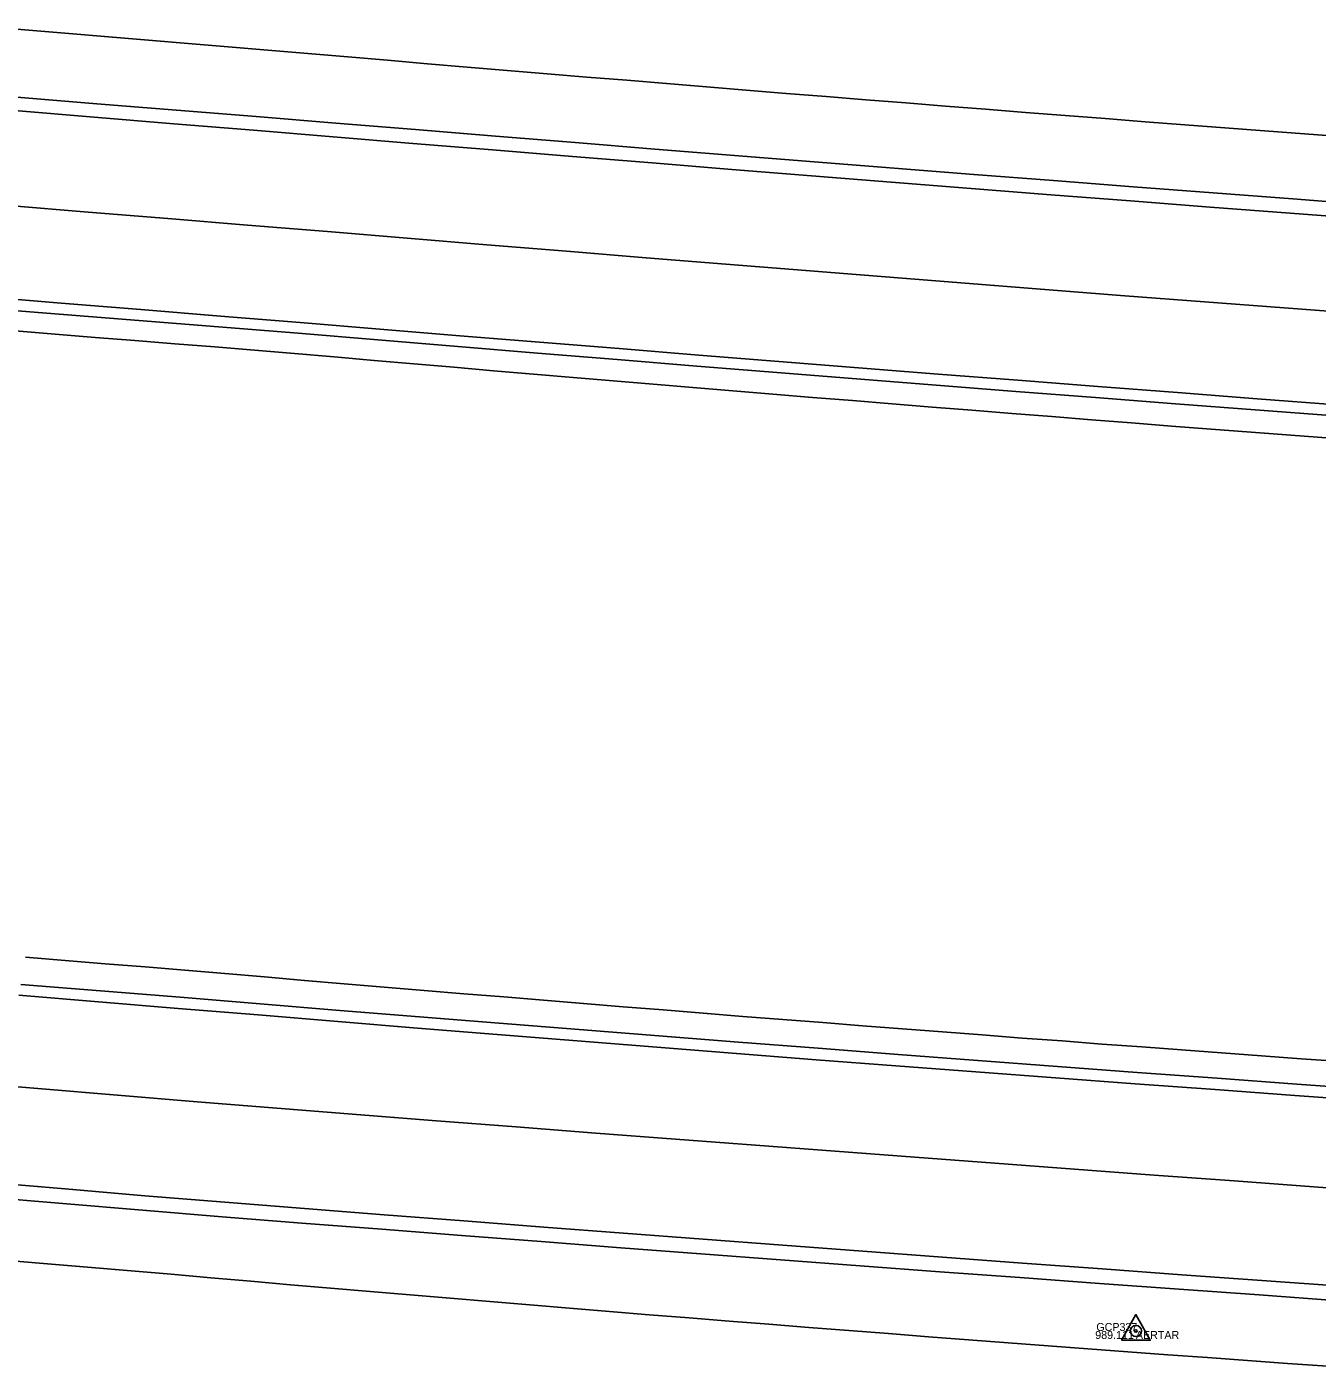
# Model space of a CAD drawing. Extents: x 2065431 to 2068157, y 709104 to 709719.
# Drawn here: x 2067834.4 to 2067995.7, y 709227.6 to 709395.1 of the extents above; entities that cross this region are included whole.
import ezdxf

# ---------------------------------------------------------------- set-up
doc = ezdxf.new("R2010")
doc.units = 0
for name, color, linetype in [('DT_X_Terrain_Boundary', 7, 'Continuous'), ('PM_X_Edge_Line', 7, 'Continuous'), ('PM_X_Lane_Line', 7, 'Continuous'), ('PV_X_EOP', 7, 'Continuous'), ('PV_X_Shoulder_Rumble_Strip', 7, 'Continuous'), ('SV_P_Aerial_Targets', 7, 'Continuous'), ('SV_X_Mon_Cells_Found', 7, 'Continuous'), ('SV_X_Text_Elevation', 7, 'Continuous'), ('SV_X_Text_Name', 7, 'Continuous')]:
    doc.layers.add(name, color=color, linetype=linetype)

msp = doc.modelspace()

# ---------------------------------------------------------------- linework, layer by layer
at = {"layer": 'DT_X_Terrain_Boundary'}
for points in [[(2067999.13, 709381.3), (2067994.14, 709381.67), (2067989.15, 709382.05), (2067984.17, 709382.43), (2067979.18, 709382.81), (2067974.2, 709383.19), (2067969.21, 709383.58), (2067964.23, 709383.97), (2067959.24, 709384.36), (2067954.26, 709384.75), (2067949.27, 709385.14), (2067944.29, 709385.54), (2067939.3, 709385.93), (2067934.32, 709386.33), (2067929.34, 709386.74), (2067924.35, 709387.14), (2067919.37, 709387.55), (2067914.39, 709387.96), (2067909.4, 709388.37), (2067904.42, 709388.78), (2067899.44, 709389.2), (2067894.46, 709389.61), (2067889.47, 709390.03), (2067884.49, 709390.45), (2067879.51, 709390.88), (2067874.53, 709391.3), (2067869.55, 709391.73), (2067864.56, 709392.15), (2067859.58, 709392.57), (2067854.6, 709392.98), (2067849.61, 709393.4), (2067844.63, 709393.81), (2067839.65, 709394.23), (2067834.67, 709394.64), (2067829.68, 709395.06)], [(2067832.97, 709357.04), (2067837.96, 709356.64), (2067842.94, 709356.24), (2067847.93, 709355.85), (2067852.91, 709355.45), (2067857.9, 709355.06), (2067862.88, 709354.66), (2067867.86, 709354.23), (2067872.84, 709353.79), (2067877.82, 709353.36), (2067882.8, 709352.93), (2067887.79, 709352.5), (2067892.77, 709352.07), (2067897.75, 709351.65), (2067902.73, 709351.23), (2067907.71, 709350.81), (2067912.7, 709350.39), (2067917.68, 709349.97), (2067922.66, 709349.56), (2067927.65, 709349.15), (2067932.63, 709348.74), (2067937.61, 709348.33), (2067942.6, 709347.93), (2067947.58, 709347.52), (2067952.56, 709347.12), (2067957.55, 709346.72), (2067962.53, 709346.33), (2067967.52, 709345.93), (2067972.5, 709345.54), (2067977.49, 709345.15), (2067982.47, 709344.77), (2067987.46, 709344.38), (2067992.44, 709344), (2067997.43, 709343.62)], [(2067998.72, 709265.71), (2067993.73, 709266.07), (2067988.75, 709266.43), (2067983.76, 709266.8), (2067978.77, 709267.17), (2067973.79, 709267.54), (2067968.8, 709267.91), (2067963.82, 709268.29), (2067958.83, 709268.66), (2067953.84, 709269.04), (2067948.86, 709269.43), (2067943.87, 709269.81), (2067938.89, 709270.2), (2067933.9, 709270.59), (2067928.92, 709270.98), (2067923.93, 709271.37), (2067918.95, 709271.77), (2067913.97, 709272.17), (2067908.98, 709272.57), (2067904, 709272.98), (2067899.02, 709273.38), (2067894.03, 709273.79), (2067889.05, 709274.2), (2067884.07, 709274.62), (2067879.08, 709275.03), (2067874.1, 709275.45), (2067869.12, 709275.87), (2067864.14, 709276.3), (2067859.16, 709276.72), (2067854.17, 709277.14), (2067849.19, 709277.54), (2067844.2, 709277.94), (2067839.22, 709278.34), (2067834.24, 709278.75)], [(2067832.52, 709240.82), (2067837.5, 709240.4), (2067842.48, 709239.97), (2067847.46, 709239.55), (2067852.44, 709239.13), (2067857.42, 709238.69), (2067862.41, 709238.26), (2067867.39, 709237.83), (2067872.37, 709237.4), (2067877.35, 709236.97), (2067882.33, 709236.55), (2067887.32, 709236.13), (2067892.3, 709235.72), (2067897.28, 709235.3), (2067902.26, 709234.89), (2067907.25, 709234.48), (2067912.23, 709234.08), (2067917.21, 709233.68), (2067922.2, 709233.28), (2067927.18, 709232.88), (2067932.17, 709232.49), (2067937.15, 709232.1), (2067942.14, 709231.71), (2067947.12, 709231.32), (2067952.11, 709230.94), (2067957.09, 709230.56), (2067962.08, 709230.19), (2067967.06, 709229.81), (2067972.05, 709229.44), (2067977.04, 709229.08), (2067982.02, 709228.71), (2067987.01, 709228.35), (2067992, 709227.99), (2067996.99, 709227.64)]]:
    msp.add_lwpolyline(points, dxfattribs=at)
at = {"layer": 'PM_X_Edge_Line'}
for points in [[(2067832.85, 709384.58), (2067842.81, 709383.76), (2067852.78, 709382.94), (2067862.75, 709382.13), (2067872.71, 709381.31), (2067882.68, 709380.48), (2067892.64, 709379.66), (2067902.61, 709378.85), (2067912.58, 709378.04), (2067922.55, 709377.23), (2067932.51, 709376.44), (2067942.48, 709375.64), (2067952.45, 709374.86), (2067962.42, 709374.07), (2067972.39, 709373.3), (2067982.36, 709372.53), (2067992.33, 709371.76), (2068002.3, 709371)], [(2067828.73, 709361.35), (2067838.7, 709360.53), (2067848.66, 709359.71), (2067858.63, 709358.9), (2067868.6, 709358.09), (2067878.56, 709357.26), (2067888.53, 709356.45), (2067898.5, 709355.64), (2067908.46, 709354.83), (2067918.43, 709354.03), (2067928.4, 709353.24), (2067938.37, 709352.44), (2067948.34, 709351.66), (2067958.31, 709350.88), (2067968.28, 709350.1), (2067978.25, 709349.33), (2067988.22, 709348.57), (2067998.19, 709347.81)], [(2067833.42, 709274.02), (2067843.39, 709273.2), (2067853.35, 709272.37), (2067863.32, 709271.54), (2067873.28, 709270.71), (2067883.25, 709269.9), (2067893.22, 709269.09), (2067903.19, 709268.29), (2067913.15, 709267.5), (2067923.12, 709266.72), (2067933.09, 709265.94), (2067943.06, 709265.18), (2067953.04, 709264.42), (2067963.01, 709263.67), (2067972.98, 709262.94), (2067982.95, 709262.21), (2067992.93, 709261.49), (2068002.9, 709260.77)], [(2067829.26, 709250.65), (2067839.22, 709249.8), (2067849.18, 709248.95), (2067859.15, 709248.13), (2067869.12, 709247.35), (2067879.09, 709246.57), (2067889.06, 709245.79), (2067899.03, 709245.02), (2067909, 709244.26), (2067918.97, 709243.5), (2067928.94, 709242.75), (2067938.92, 709242), (2067948.89, 709241.26), (2067958.86, 709240.53), (2067968.83, 709239.8), (2067978.81, 709239.07), (2067988.78, 709238.36), (2067998.76, 709237.65)]]:
    msp.add_lwpolyline(points, dxfattribs=at)
at = {"layer": 'PM_X_Lane_Line'}
for points in [[(2067832.11, 709372.73), (2067842.08, 709371.91), (2067852.05, 709371.09), (2067862.01, 709370.28), (2067871.98, 709369.47), (2067881.95, 709368.65), (2067891.91, 709367.82), (2067901.88, 709367), (2067911.85, 709366.19), (2067921.81, 709365.38), (2067931.78, 709364.58), (2067941.75, 709363.79), (2067951.72, 709363), (2067961.69, 709362.22), (2067971.66, 709361.45), (2067981.63, 709360.68), (2067991.6, 709359.92), (2068001.57, 709359.17)], [(2067825.81, 709263.2), (2067835.77, 709262.36), (2067845.74, 709261.53), (2067855.71, 709260.7), (2067865.67, 709259.88), (2067875.64, 709259.1), (2067885.61, 709258.32), (2067895.58, 709257.55), (2067905.55, 709256.78), (2067915.52, 709256.02), (2067925.49, 709255.26), (2067935.46, 709254.5), (2067945.44, 709253.75), (2067955.41, 709253), (2067965.38, 709252.26), (2067975.35, 709251.52), (2067985.33, 709250.79), (2067995.3, 709250.05), (2068005.27, 709249.33)]]:
    msp.add_lwpolyline(points, dxfattribs=at)
at = {"layer": 'PV_X_EOP'}
for points in [[(2067829.68, 709395.06), (2067834.67, 709394.64), (2067839.65, 709394.23), (2067844.63, 709393.81), (2067849.61, 709393.4), (2067854.6, 709392.98), (2067859.58, 709392.57), (2067864.56, 709392.15), (2067869.55, 709391.73), (2067874.53, 709391.3), (2067879.51, 709390.88), (2067884.49, 709390.45), (2067889.47, 709390.03), (2067894.46, 709389.61), (2067899.44, 709389.2), (2067904.42, 709388.78), (2067909.4, 709388.37), (2067914.39, 709387.96), (2067919.37, 709387.55), (2067924.35, 709387.14), (2067929.34, 709386.74), (2067934.32, 709386.33), (2067939.3, 709385.93), (2067944.29, 709385.54), (2067949.27, 709385.14), (2067954.26, 709384.75), (2067959.24, 709384.36), (2067964.23, 709383.97), (2067969.21, 709383.58), (2067974.2, 709383.19), (2067979.18, 709382.81), (2067984.17, 709382.43), (2067989.15, 709382.05), (2067994.14, 709381.67), (2067999.13, 709381.3)], [(2067832.97, 709357.04), (2067837.96, 709356.64), (2067842.94, 709356.24), (2067847.93, 709355.85), (2067852.91, 709355.45), (2067857.9, 709355.06), (2067862.88, 709354.66), (2067867.86, 709354.23), (2067872.84, 709353.79), (2067877.82, 709353.36), (2067882.8, 709352.93), (2067887.79, 709352.5), (2067892.77, 709352.07), (2067897.75, 709351.65), (2067902.73, 709351.23), (2067907.71, 709350.81), (2067912.7, 709350.39), (2067917.68, 709349.97), (2067922.66, 709349.56), (2067927.65, 709349.15), (2067932.63, 709348.74), (2067937.61, 709348.33), (2067942.6, 709347.93), (2067947.58, 709347.52), (2067952.56, 709347.12), (2067957.55, 709346.72), (2067962.53, 709346.33), (2067967.52, 709345.93), (2067972.5, 709345.54), (2067977.49, 709345.15), (2067982.47, 709344.77), (2067987.46, 709344.38), (2067992.44, 709344), (2067997.43, 709343.62)], [(2067834.24, 709278.75), (2067839.22, 709278.34), (2067844.2, 709277.94), (2067849.19, 709277.54), (2067854.17, 709277.14), (2067859.16, 709276.72), (2067864.14, 709276.3), (2067869.12, 709275.87), (2067874.1, 709275.45), (2067879.08, 709275.03), (2067884.07, 709274.62), (2067889.05, 709274.2), (2067894.03, 709273.79), (2067899.02, 709273.38), (2067904, 709272.98), (2067908.98, 709272.57), (2067913.97, 709272.17), (2067918.95, 709271.77), (2067923.93, 709271.37), (2067928.92, 709270.98), (2067933.9, 709270.59), (2067938.89, 709270.2), (2067943.87, 709269.81), (2067948.86, 709269.43), (2067953.84, 709269.04), (2067958.83, 709268.66), (2067963.82, 709268.29), (2067968.8, 709267.91), (2067973.79, 709267.54), (2067978.77, 709267.17), (2067983.76, 709266.8), (2067988.75, 709266.43), (2067993.73, 709266.07), (2067998.72, 709265.71)], [(2067832.52, 709240.82), (2067837.5, 709240.4), (2067842.48, 709239.97), (2067847.46, 709239.55), (2067852.44, 709239.13), (2067857.42, 709238.69), (2067862.41, 709238.26), (2067867.39, 709237.83), (2067872.37, 709237.4), (2067877.35, 709236.97), (2067882.33, 709236.55), (2067887.32, 709236.13), (2067892.3, 709235.72), (2067897.28, 709235.3), (2067902.26, 709234.89), (2067907.25, 709234.48), (2067912.23, 709234.08), (2067917.21, 709233.68), (2067922.2, 709233.28), (2067927.18, 709232.88), (2067932.17, 709232.49), (2067937.15, 709232.1), (2067942.14, 709231.71), (2067947.12, 709231.32), (2067952.11, 709230.94), (2067957.09, 709230.56), (2067962.08, 709230.19), (2067967.06, 709229.81), (2067972.05, 709229.44), (2067977.04, 709229.08), (2067982.02, 709228.71), (2067987.01, 709228.35), (2067992, 709227.99), (2067996.99, 709227.64)]]:
    msp.add_lwpolyline(points, dxfattribs=at)
at = {"layer": 'PV_X_Shoulder_Rumble_Strip'}
for points in [[(2067833.18, 709386.26), (2067843.15, 709385.45), (2067853.12, 709384.65), (2067863.08, 709383.85), (2067873.05, 709383.03), (2067883.02, 709382.21), (2067892.98, 709381.39), (2067902.95, 709380.58), (2067912.92, 709379.78), (2067922.89, 709378.98), (2067932.85, 709378.19), (2067942.82, 709377.4), (2067952.79, 709376.61), (2067962.76, 709375.84), (2067972.73, 709375.07), (2067982.7, 709374.3), (2067992.67, 709373.54), (2068002.65, 709372.78)], [(2067828.48, 709359.95), (2067838.44, 709359.14), (2067848.41, 709358.35), (2067858.38, 709357.56), (2067868.35, 709356.75), (2067878.31, 709355.92), (2067888.28, 709355.1), (2067898.25, 709354.28), (2067908.21, 709353.46), (2067918.18, 709352.66), (2067928.15, 709351.86), (2067938.12, 709351.06), (2067948.08, 709350.27), (2067958.05, 709349.49), (2067968.02, 709348.71), (2067977.99, 709347.94), (2067987.96, 709347.18), (2067997.94, 709346.42)], [(2067833.66, 709275.34), (2067843.63, 709274.55), (2067853.6, 709273.75), (2067863.57, 709272.94), (2067873.53, 709272.12), (2067883.5, 709271.31), (2067893.47, 709270.51), (2067903.44, 709269.71), (2067913.4, 709268.93), (2067923.37, 709268.15), (2067933.34, 709267.38), (2067943.32, 709266.61), (2067953.29, 709265.86), (2067963.26, 709265.11), (2067973.23, 709264.37), (2067983.2, 709263.64), (2067993.18, 709262.91), (2068003.15, 709262.19)], [(2067828.93, 709248.83), (2067838.9, 709247.99), (2067848.86, 709247.14), (2067858.83, 709246.32), (2067868.8, 709245.53), (2067878.77, 709244.75), (2067888.74, 709243.98), (2067898.71, 709243.21), (2067908.68, 709242.44), (2067918.65, 709241.68), (2067928.62, 709240.93), (2067938.59, 709240.19), (2067948.56, 709239.45), (2067958.54, 709238.71), (2067968.51, 709237.98), (2067978.48, 709237.26), (2067988.46, 709236.54), (2067998.43, 709235.83)]]:
    msp.add_lwpolyline(points, dxfattribs=at)
at = {"layer": 'SV_P_Aerial_Targets'}
msp.add_lwpolyline([(2067971.25, 709230.88), (2067974.85, 709230.88), (2067973.05, 709234.1)], close=True, dxfattribs=at)
for radius in [0.7, 0.16]:
    msp.add_circle((2067973.05, 709232.04), radius, dxfattribs=at)

# ---------------------------------------------------------------- texts
at = {"layer": 'SV_X_Mon_Cells_Found'}
msp.add_text('GCP337', height=1, dxfattribs=at).set_placement((2067968.11, 709232.04))
at = {"layer": 'SV_X_Text_Elevation'}
msp.add_text('AERTAR', height=1, dxfattribs=at).set_placement((2067973.05, 709231.04))
at = {"layer": 'SV_X_Text_Name'}
msp.add_text('989.111', height=1, dxfattribs=at).set_placement((2067967.97, 709231.04))

doc.saveas('drawing.dxf')
